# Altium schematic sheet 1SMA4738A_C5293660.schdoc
size 127 x 101 mm
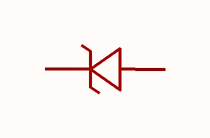
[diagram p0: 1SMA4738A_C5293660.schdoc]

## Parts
D?  1sma4738a_c5293660  [SMAG_L4.3-W2.6-LS5.3-RD]  (value not drawn)

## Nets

Not connected (* = marked no-connect by the designer): D? 1(C) 2(A)

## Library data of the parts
D? = 1sma4738a_c5293660: 二极管配置:1个独立式;稳压值(标称值):8.2V;稳压值(范围值):-;耗散功率(Pd):1W;; Manufacturer: CJ(江苏长电/长晶); AddInBom: yes; ModelId: 3cd8680d946b497db8ea5837610a9736; ModelTransform: 208.661,102.362,0,0,0,0,0,0,0; Diode Configuration: 1个独立式; Zener Voltage(Nom): 8.2V; Reverse Leakage Current (Ir): 5uA@6V; Pd - Power Dissipation: 1W; Impedance(Zzt): 4.5Ω; Impedance(Zzk): 700Ω; Operating Junction Temperature Range: -55℃~+150℃; Tolerance: ±5%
